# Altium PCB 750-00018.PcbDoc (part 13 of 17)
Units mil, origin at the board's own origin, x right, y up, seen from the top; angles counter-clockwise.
Board outline 7086.64 x 6299.21 mil, 8 copper layers (Top Layer, L2, L3, L4, L5, L6, L7, Bottom Layer), stack 60.6 mil thick; 1356 components, 1054 nets, 4851 pads, 4296 vias.
Unrouted connection lines stored in the file: 12.
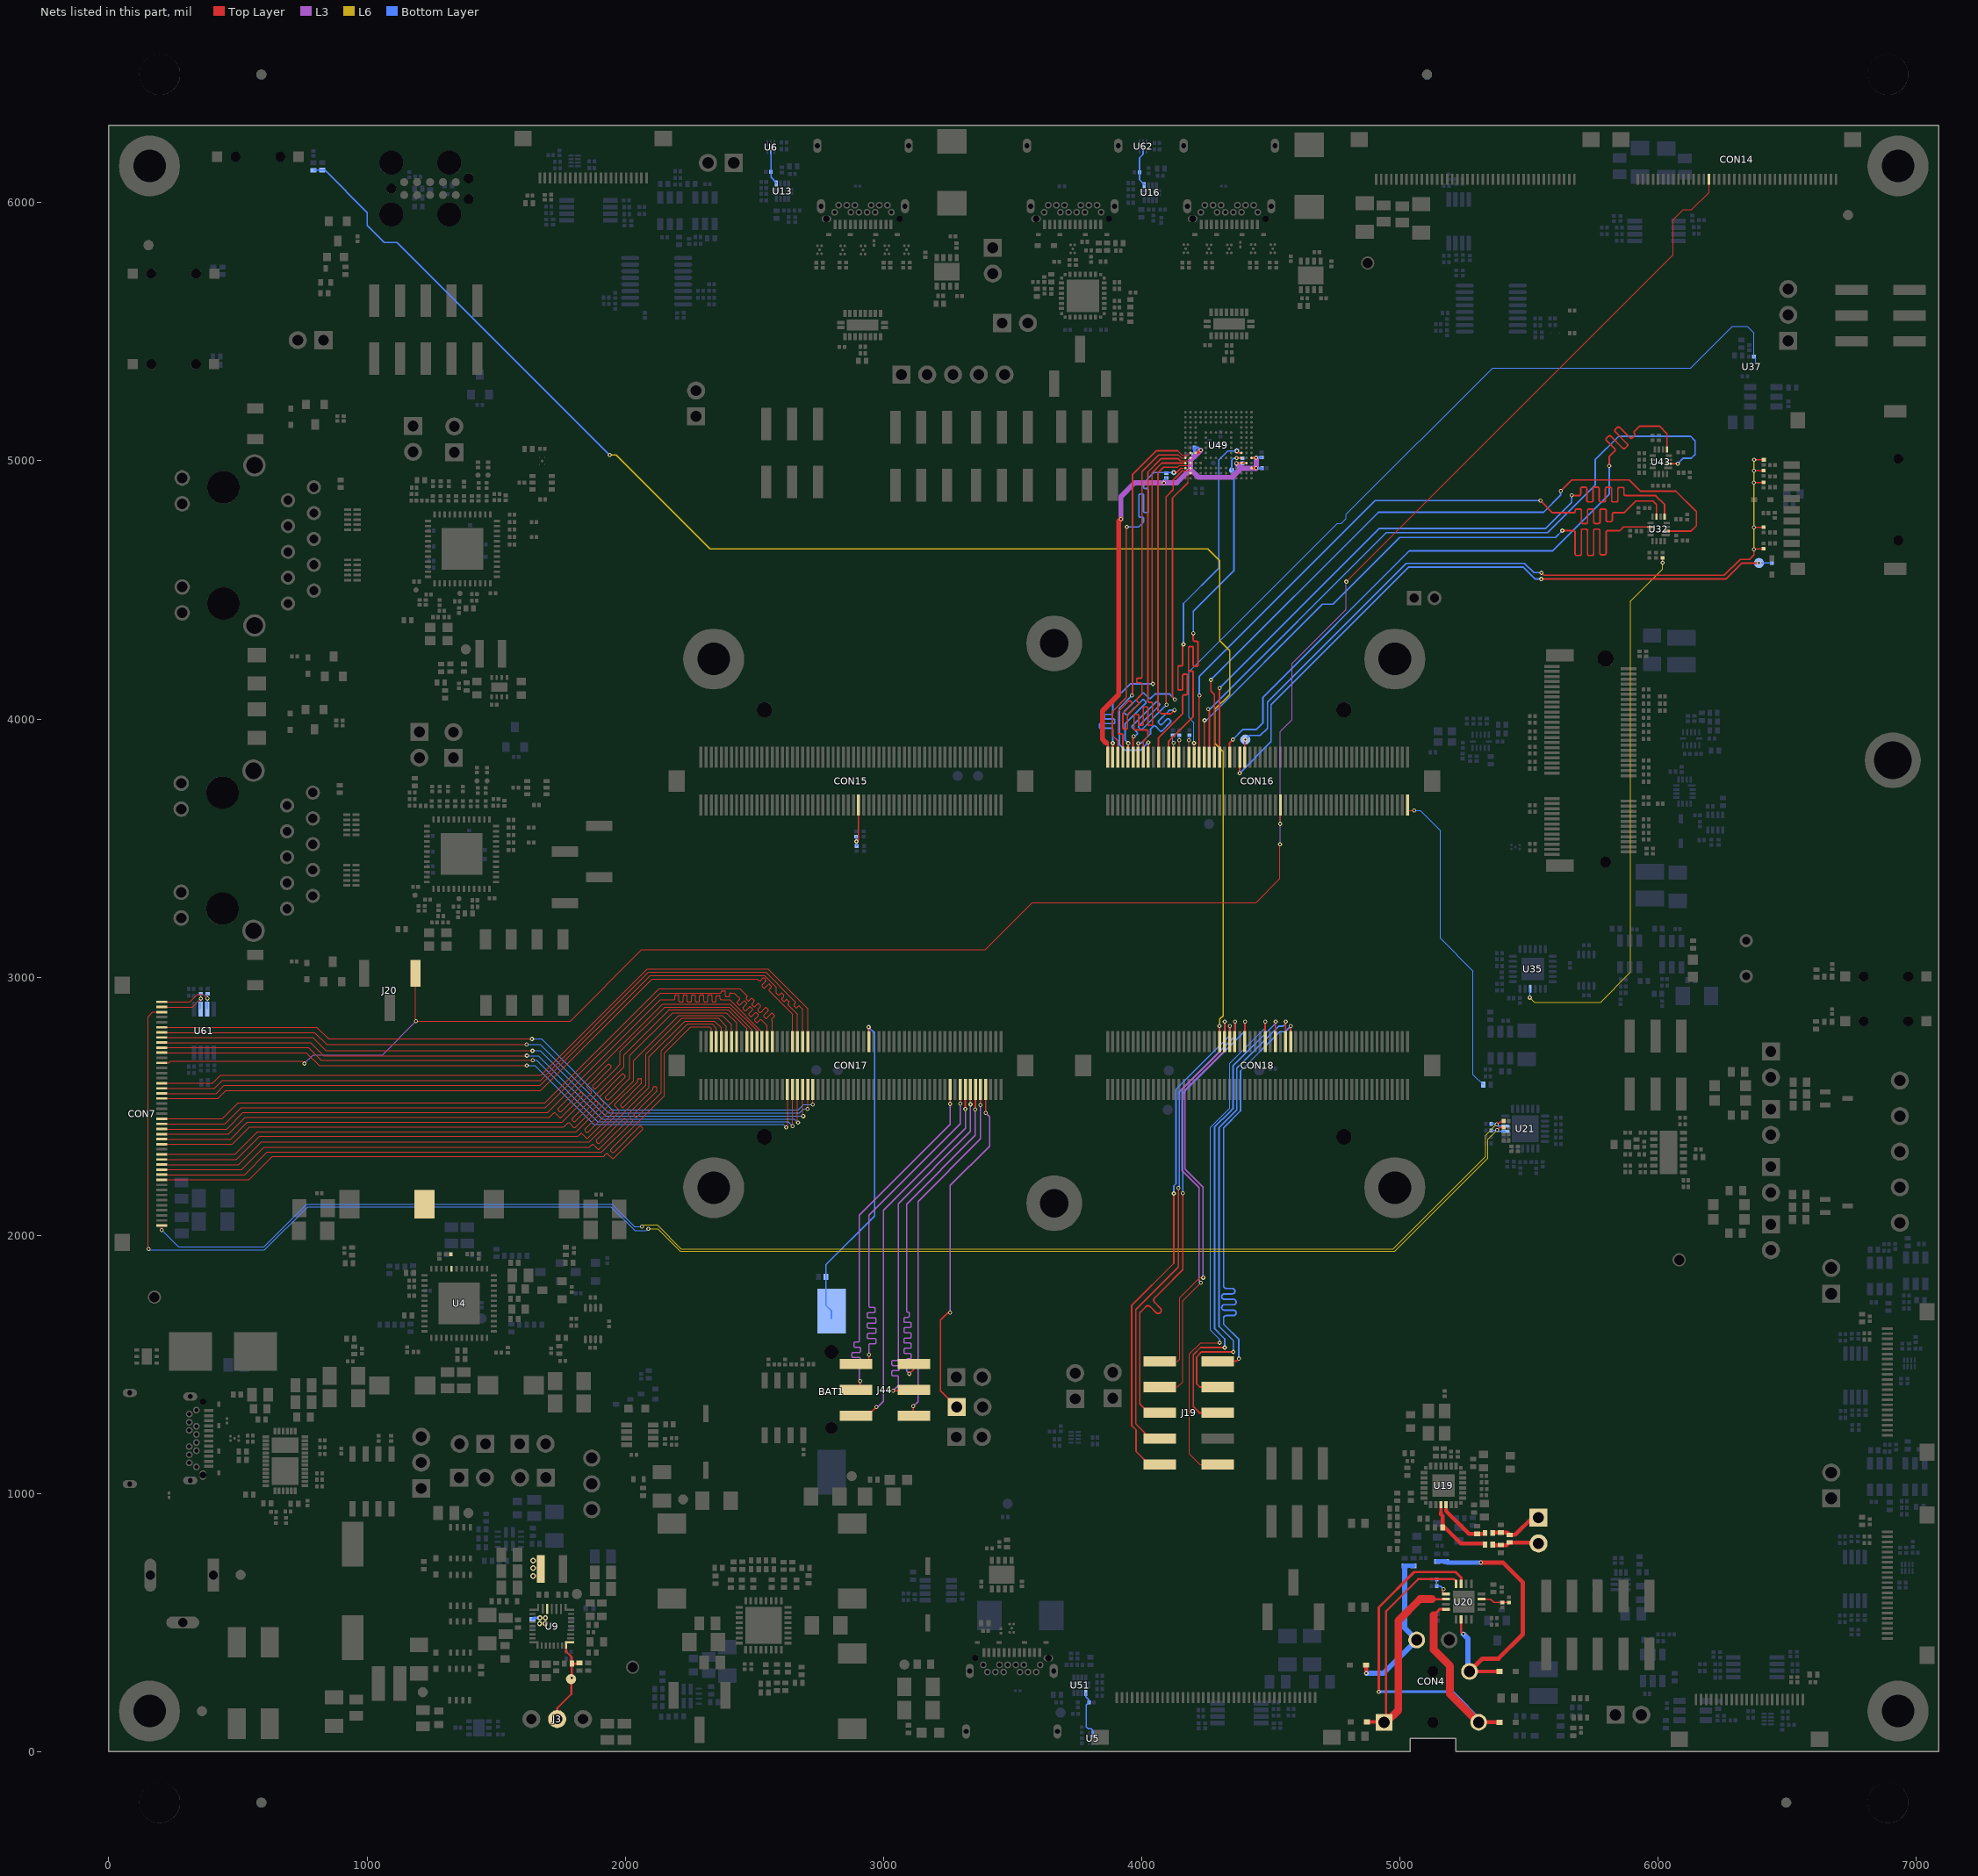
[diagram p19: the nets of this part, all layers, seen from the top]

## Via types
v1: diameter 16, hole 8, Top Layer to Bottom Layer, tented both sides, 3994 vias
v2: diameter 20, hole 10, Top Layer to Bottom Layer, tented both sides, 266 vias
v3: diameter 14, hole 7.87, Top Layer to Bottom Layer, tented both sides, 24 vias
v4: diameter 22, hole 12, Top Layer to Bottom Layer, tented both sides, 8 vias
v5: diameter 24, hole 12, Top Layer to Bottom Layer, tented both sides, 4 vias

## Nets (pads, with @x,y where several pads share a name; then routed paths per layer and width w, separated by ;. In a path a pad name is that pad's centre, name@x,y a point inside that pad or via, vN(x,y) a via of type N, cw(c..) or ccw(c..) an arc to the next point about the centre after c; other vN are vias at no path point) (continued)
RGB_B2: CON7.20 CON17.84 | length 2876
  Top Layer w4: CON7.20@204.84,2530.21 422.51,2530.21 453.35,2561.06 1671.84,2561.06 2104.1,2993.32 2511.42,2993.32 2516.58,2988.16 2517.99,2986.75 ccw(c2520.82,2989.58) 2523.65,2986.75 2532.61,2995.71 cw(c2535.44,2992.88) 2538.27,2995.71 2543.92,2990.05 cw(c2541.09,2987.22) 2543.92,2984.4 2529.86,2970.34 ccw(c2532.69,2967.51) 2529.86,2964.68 2535.52,2959.02 ccw(c2538.35,2961.85) 2541.18,2959.02 2553.44,2971.29 cw(c2556.27,2968.46) 2559.1,2971.29 2564.75,2965.63 cw(c2561.93,2962.8) 2564.75,2959.97 2557.59,2952.81 ccw(c2560.42,2949.98) 2557.59,2947.15 2568.48,2936.26 2647.64,2857.1 CON17.84@2647.64,2750.44
RGB_B3: CON7.19 CON17.82 | length 2876
  Top Layer w4: CON7.19@204.84,2549.9 415.29,2549.9 446.14,2580.74 1670.54,2580.74 2096.34,3006.54 2539.58,3006.54 2585.24,2960.88 2585.24,2938.18 2590.02,2933.4 2591.44,2931.98 ccw(c2594.27,2934.81) 2597.09,2931.98 2601.78,2936.67 cw(c2604.61,2933.84) 2607.43,2936.67 2613.09,2931.01 cw(c2610.26,2928.18) 2613.09,2925.35 2606.9,2919.16 ccw(c2609.73,2916.33) 2606.9,2913.5 2612.56,2907.85 ccw(c2615.38,2910.67) 2618.21,2907.85 2622.31,2911.94 cw(c2625.14,2909.11) 2627.97,2911.94 2633.62,2906.29 cw(c2630.8,2903.46) 2633.62,2900.63 2631.04,2898.04 ccw(c2633.86,2895.21) 2631.04,2892.38 2649.19,2874.23 2667.33,2856.09 CON17.82@2667.33,2750.44
RGB_B4: CON7.18 CON17.80 | length 2876
  Top Layer w4: CON7.18@204.84,2569.58 408.87,2569.58 439.72,2600.43 1671.91,2600.43 2090.99,3019.51 2543.34,3019.51 2645.82,2917.02 2658.55,2904.3 cw(c2655.72,2901.47) 2658.55,2898.64 2653.81,2893.89 ccw(c2656.63,2891.06) 2653.81,2888.24 2659.46,2882.58 ccw(c2662.29,2885.41) 2665.12,2882.58 2669.87,2887.33 cw(c2672.69,2884.5) 2675.52,2887.33 2684.26,2878.59 2687.01,2875.84 CON17.80@2687.01,2750.44
RGB_B5: CON7.17 CON17.78 | length 2876
  Top Layer w4: CON7.17@204.84,2589.26 401.66,2589.26 432.51,2620.11 1672.96,2620.11 2084.67,3031.82 2552.19,3031.82 2706.7,2877.32 CON17.78@2706.7,2750.44
"RGB_BL_PWM / LVDS_E_BL_PWM / PWM_2": CON7.13 CON14.26 CON16.70 J20.1 | length 8311.2
  Top Layer w4: CON7.13@204.84,2668.13 232.85,2668.13 239.73,2675.01 748.47,2675.01 v1(757.71,2665.78) ; v1@1187.99,2829.35 J20.1@1187.99,3015.01 ; v1(1189.57,2829.35) 1786.94,2829.35 2063.76,3106.18 3393.79,3106.18 3576.65,3289.03 4443.01,3289.03 4535.65,3381.68 v1(4535.65,3514.53) ; v1(4536.33,3593.67) 4536.8,3594.14 CON16.70@4536.8,3668.45 ; v1(4792.41,4531.9) 6058.03,5797.52 6058.03,5934.45 6096.47,5972.89 6129.93,5972.89 6196.76,6039.72 CON14.26@6196.76,6090.59
  L3 w4: v1(757.71,2665.78) 791.32,2699.39 1059.6,2699.39 v1(1189.57,2829.35) ; v1(4535.65,3514.53) 4536.33,3515.21 v1(4536.33,3593.67) 4536.33,3951.62 4582.66,3997.95 4582.66,4215.21 4792.41,4424.95 v1(4792.41,4531.9)
RGB_CS#: CON7.6 CON17.75 | length 2721.5
  Top Layer w4: CON7.6@204.84,2805.8 805.45,2805.8 850.45,2760.8 v1(1638.62,2760.8) ; v1(2726.17,2506.69) 2726.38,2506.9 CON17.75@2726.38,2565.4
  Bottom Layer w4: v1(1638.62,2760.8) 1674.63,2760.8 1949.87,2485.57 2669.27,2485.57 2690.4,2506.69 v1(2726.17,2506.69)
RGB_DE: CON7.8 CON17.79 | length 2714.9
  Top Layer w4: CON7.8@204.84,2766.43 789.15,2766.43 840.58,2714.99 v1(1640.8,2714.99) ; CON17.79@2687.01,2565.4 2687.01,2464.06 v1(2689.19,2461.88)
  Bottom Layer w4: v1(1640.8,2714.99) 1670.05,2714.99 1923.16,2461.88 v1(2689.19,2461.88)
RGB_DISP: CON7.9 CON17.81 | length 2722
  Top Layer w4: CON7.9@204.84,2746.75 780.99,2746.75 831.78,2695.96 v1(1618.79,2695.96) ; CON17.81@2667.33,2565.4 2667.33,2438.15 v1(2668.91,2436.57)
  Bottom Layer w4: v1(1618.79,2695.96) 1664.24,2695.96 1909.19,2451 2654.47,2451 v1(2668.91,2436.57)
RGB_G0: CON7.29 CON17.102 | length 2876
  Top Layer w4: CON7.29@204.84,2353.04 479.37,2353.04 545.75,2419.43 1761.46,2419.43 1775.26,2433.24 1776.68,2434.65 cw(c1780.07,2431.26) 1783.47,2434.65 1799.31,2418.81 ccw(c1802.7,2422.2) 1806.08,2418.8 1894.03,2506.74 ccw(c1890.63,2510.14) 1894.03,2513.53 1889.5,2518.06 ccw(c1886.11,2514.66) 1882.71,2518.06 1806.09,2441.44 cw(c1802.7,2444.83) 1799.31,2441.44 1794.78,2445.96 cw(c1798.17,2449.36) 1794.78,2452.75 1895.35,2553.32 1896.76,2554.73 1994.34,2652.31 1994.34,2698.26 2169.49,2873.42 2397.71,2873.42 2470.47,2800.65 CON17.102@2470.47,2750.44
RGB_G1: CON7.28 CON17.100 | length 2876.4
  Top Layer w4: CON7.28@204.84,2372.73 471.22,2372.73 536.6,2438.11 1755.14,2438.11 1866.45,2549.43 1867.86,2550.84 ccw(c1864.47,2554.23) 1867.87,2557.62 1852.02,2573.47 cw(c1855.42,2576.86) 1852.02,2580.25 1932.91,2661.14 cw(c1936.3,2657.75) 1939.7,2661.14 1944.22,2656.62 cw(c1940.83,2653.22) 1944.22,2649.83 1874.65,2580.26 ccw(c1878.05,2576.86) 1874.65,2573.47 1879.18,2568.94 ccw(c1882.57,2572.34) 1885.97,2568.94 1968.95,2651.93 1970.37,2653.34 1979.86,2662.84 1979.86,2712.01 2152.29,2884.44 2402.59,2884.44 2489.16,2797.87 2489.16,2751.44 CON17.100@2490.16,2750.44
RGB_G2: CON7.27 CON17.98 | length 2876
  Top Layer w4: CON7.27@204.84,2392.41 463.06,2392.41 527.48,2456.83 1705.85,2456.83 1720.83,2471.81 1722.25,2473.23 cw(c1725.64,2469.83) 1729.03,2473.23 1744.86,2457.4 ccw(c1748.27,2460.78) 1751.65,2457.38 1835.71,2541.44 ccw(c1832.32,2544.83) 1835.71,2548.23 1831.19,2552.75 ccw(c1827.79,2549.36) 1824.4,2552.75 1751.66,2480.02 cw(c1748.27,2483.41) 1744.87,2480.02 1740.35,2484.54 cw(c1743.74,2487.94) 1740.35,2491.33 1837.05,2588.03 1838.46,2589.44 2145.39,2896.38 2406.99,2896.38 2509.85,2793.52 CON17.98@2509.85,2750.44
RGB_G3: CON7.26 CON17.96 | length 2877.5
  Top Layer w4: CON7.26@204.84,2412.1 456,2412.1 519.45,2475.55 1698.59,2475.55 2135.65,2912.61 2185.99,2912.61 2187.99,2912.61 ccw(c2187.99,2916.61) 2191.99,2916.61 2191.99,2926.97 cw(c2195.99,2926.97) 2195.99,2930.97 2203.99,2930.97 cw(c2203.99,2926.97) 2207.99,2926.97 2207.99,2908.38 ccw(c2211.99,2908.38) 2211.99,2904.38 2219.99,2904.38 ccw(c2219.99,2908.38) 2223.99,2908.38 2223.99,2926.97 cw(c2227.99,2926.97) 2227.99,2930.97 2235.99,2930.97 cw(c2235.99,2926.97) 2239.99,2926.97 2239.99,2908.38 ccw(c2243.99,2908.38) 2243.99,2904.38 2251.99,2904.38 ccw(c2251.99,2908.38) 2255.99,2908.38 2255.99,2926.97 cw(c2259.99,2926.97) 2259.99,2930.97 2267.99,2930.97 cw(c2267.99,2926.97) 2271.99,2926.97 2271.99,2908.38 ccw(c2275.99,2908.38) 2275.99,2904.38 2283.99,2904.38 ccw(c2283.99,2908.38) 2287.99,2908.38 2287.99,2926.97 cw(c2291.99,2926.97) 2291.99,2930.97 2299.99,2930.97 cw(c2299.99,2926.97) 2303.99,2926.97 2303.99,2908.38 ccw(c2307.99,2908.38) 2307.99,2904.38 2315.99,2904.38 ccw(c2315.99,2908.38) 2319.99,2908.38 2319.99,2926.97 cw(c2323.99,2926.97) 2323.99,2930.97 2331.99,2930.97 cw(c2331.99,2926.97) 2335.99,2926.97 2335.99,2908.38 ccw(c2339.99,2908.38) 2339.99,2904.38 2347.99,2904.38 ccw(c2347.99,2908.38) 2351.99,2908.38 2351.99,2924.51 cw(c2355.99,2924.51) 2355.99,2928.51 2363.99,2928.51 cw(c2363.99,2924.51) 2367.99,2924.51 2367.99,2916.61 ccw(c2371.99,2916.61) 2371.99,2912.61 2381.78,2912.61 2404.57,2912.61 2529.53,2787.65 CON17.96@2529.53,2750.44
RGB_G4: CON7.25 CON17.94 | length 2876
  Top Layer w4: CON7.25@204.84,2431.78 449.32,2431.78 511.81,2494.27 1691.07,2494.27 2135.77,2938.97 2366.1,2938.97 2368.1,2938.97 ccw(c2368.1,2942.97) 2372.1,2942.97 2372.1,2943.24 cw(c2376.1,2943.24) 2376.1,2947.24 2384.1,2947.24 cw(c2384.1,2943.24) 2388.1,2943.24 2388.1,2928.48 ccw(c2392.1,2928.48) 2392.1,2924.48 2400.1,2924.48 ccw(c2400.1,2928.48) 2404.1,2928.48 2404.1,2934.97 cw(c2408.1,2934.97) 2408.1,2938.97 2422.06,2938.97 2422.25,2938.97 2429.32,2931.9 2442.05,2919.17 cw(c2439.22,2916.34) 2442.05,2913.51 2433.53,2904.99 ccw(c2436.36,2902.16) 2433.53,2899.34 2439.19,2893.68 ccw(c2442.02,2896.51) 2444.85,2893.68 2457.99,2906.83 cw(c2460.82,2904) 2463.65,2906.83 2469.31,2901.17 cw(c2466.48,2898.34) 2469.31,2895.51 2456.16,2882.37 ccw(c2458.99,2879.54) 2456.16,2876.71 2461.82,2871.05 ccw(c2464.64,2873.88) 2467.47,2871.05 2480.62,2884.2 cw(c2483.45,2881.37) 2486.28,2884.2 2491.93,2878.54 cw(c2489.1,2875.71) 2491.93,2872.88 2478.79,2859.74 ccw(c2481.62,2856.91) 2478.79,2854.08 2484.44,2848.42 ccw(c2487.27,2851.25) 2490.1,2848.42 2503.25,2861.57 cw(c2506.08,2858.74) 2508.9,2861.57 2514.56,2855.91 cw(c2511.73,2853.09) 2514.56,2850.26 2501.41,2837.11 ccw(c2504.24,2834.28) 2501.41,2831.45 2507.07,2825.8 ccw(c2509.9,2828.63) 2512.73,2825.8 2521.25,2834.31 cw(c2524.07,2831.49) 2526.9,2834.31 2541.79,2819.43 2549.22,2812 CON17.94@2549.22,2750.44
RGB_G5: CON7.24 CON17.92 | length 2876
  Top Layer w4: CON7.24@204.84,2451.47 439.13,2451.47 500.56,2512.89 1689.3,2512.89 2131.76,2955.35 2444.01,2955.35 2458.09,2941.27 2470.82,2928.54 cw(c2467.99,2925.71) 2470.82,2922.88 2468.86,2920.92 ccw(c2471.69,2918.09) 2468.86,2915.27 2474.52,2909.61 ccw(c2477.35,2912.44) 2480.18,2909.61 2486.72,2916.16 cw(c2489.55,2913.33) 2492.38,2916.16 2498.04,2910.5 cw(c2495.21,2907.67) 2498.04,2904.84 2491.49,2898.3 ccw(c2494.32,2895.47) 2491.49,2892.64 2497.15,2886.98 ccw(c2499.98,2889.81) 2502.81,2886.98 2512.05,2896.23 ; 2512.05,2896.23 cw(c2514.88,2893.4) 2517.71,2896.23 2523.36,2890.57 cw(c2520.53,2887.74) 2523.36,2884.91 2514.12,2875.67 ccw(c2516.95,2872.84) 2514.12,2870.01 2519.78,2864.35 ccw(c2522.61,2867.18) 2525.43,2864.35 2541.59,2880.51 cw(c2544.42,2877.68) 2547.25,2880.51 2552.91,2874.86 cw(c2550.08,2872.03) 2552.91,2869.2 2536.75,2853.04 ccw(c2539.58,2850.21) 2536.75,2847.38 2542.4,2841.73 ccw(c2545.23,2844.56) 2548.06,2841.73 2565.04,2858.7 cw(c2567.87,2855.87) 2570.69,2858.7 2576.35,2853.05 cw(c2573.52,2850.22) 2576.35,2847.39 2566.99,2838.03 ccw(c2569.82,2835.2) 2566.99,2832.37 2568.9,2830.46 2568.9,2815.07 CON17.92@2568.9,2750.44
RGB_HDMI_HPD: CON7.45 R546.1 R554.2 U21.22 | length 5699.6
  Top Layer w4: v1(204.67,2020.58) 204.84,2020.75 CON7.45@204.84,2038.21
  Top Layer w5: v1(5374.88,2429.76) 5378.82,2429.76 5391.93,2442.87 R554.2@5401.82,2442.87
  L6 w4: v1(2064.93,2033.87) 2071.72,2040.65 2123.68,2040.65 2216.49,1947.84 4973.82,1947.84 5331.71,2305.73 5331.71,2387.96 5373.51,2429.76 v1(5374.88,2429.76)
  Bottom Layer w4: v1(204.67,2020.58) 268.72,1956.53 601.58,1956.53 766.25,2121.2 1949.23,2121.2 2036.56,2033.87 v1(2064.93,2033.87)
  Bottom Layer w5: R546.1@5352.93,2432.14 5372.5,2432.14 v1(5374.88,2429.76) 5381.62,2423.01 U21.22@5408.49,2423.01
RGB_HSYNC: CON7.10 CON17.83 | length 2712.4
  Top Layer w4: CON7.10@204.84,2727.06 772.84,2727.06 821.99,2677.91 v1(1641,2677.91) ; CON17.83@2647.64,2565.4 2646.26,2564.02 2647.97,2562.31 v1(2647.97,2423.23)
  Bottom Layer w4: v1(1641,2677.91) 1656.36,2677.91 1893.62,2440.65 2630.56,2440.65 v1(2647.97,2423.23)
RGB_INT: CON7.3 R545.1 R553.2 U21.21 | length 6656.2
  Top Layer w4: v1(154.15,1946.95) 151.69,1949.41 151.69,2847.33 169.22,2864.86 CON7.3@204.84,2864.86
  Top Layer w5: v1(5376.23,2407.74) 5386.3,2417.81 R553.2@5401.82,2417.81
  L6 w4: v1(2089.15,2025.25) 2126.14,2025.25 2212.7,1938.68 4981,1938.68 5341.32,2299.01 5341.32,2372.84 v1(5376.23,2407.74)
  Bottom Layer w4: v1(154.15,1946.95) 156.7,1944.4 603.42,1944.4 770.28,2111.26 1944.34,2111.26 2037.1,2018.5 2082.41,2018.5 v1(2089.15,2025.25)
  Bottom Layer w5: R545.1@5352.93,2406.77 5375.25,2406.77 v1(5376.23,2407.74) 5380.63,2403.33 U21.21@5408.49,2403.33
RGB_R0: CON7.36 CON17.116 | length 2876
  Top Layer w4: CON7.36@204.84,2215.25 542.88,2215.25 633.69,2306.06 1916.69,2306.06 1924.44,2313.81 1925.85,2315.23 cw(c1929.25,2311.83) 1932.64,2315.23 1948.48,2299.38 ccw(c1951.87,2302.78) 1955.26,2299.38 2066.37,2410.49 ccw(c2062.98,2413.89) 2066.37,2417.28 2061.85,2421.81 ccw(c2058.45,2418.41) 2055.06,2421.81 1955.27,2322.02 cw(c1951.87,2325.41) 1948.48,2322.02 1943.95,2326.54 cw(c1947.35,2329.94) 1943.95,2333.33 2052.06,2441.44 2053.48,2442.85 2151.01,2540.39 2151.01,2705.61 2252.8,2807.4 2325.94,2807.4 2332.68,2800.66 CON17.116@2332.68,2750.44
RGB_R1: CON7.35 CON17.114 | length 2876.3
  Top Layer w4: CON7.35@204.84,2234.93 525.89,2234.93 613.61,2322.66 1909.09,2322.66 2025.78,2439.34 2027.19,2440.76 ccw(c2023.8,2444.15) 2027.19,2447.54 2011.36,2463.37 cw(c2014.75,2466.78) 2011.34,2470.16 2105.65,2564.47 ccw(c2102.25,2567.85) 2107.05,2567.85 2107.05,2570.77 cw(c2111.85,2570.77) 2111.85,2575.57 2118.25,2575.57 cw(c2118.25,2570.77) 2123.05,2570.77 2123.05,2561.23 cw(c2118.25,2561.23) 2121.65,2557.84 2033.98,2470.17 ccw(c2037.38,2466.78) 2033.98,2463.38 2038.51,2458.86 ccw(c2041.9,2462.25) 2045.3,2458.86 2137.65,2551.21 ccw(c2134.25,2554.6) 2139.05,2554.6 2139.05,2601.81 2139.05,2603.81 2139.05,2716.51 2241.15,2818.61 2336.77,2818.61 2352.36,2803.02 CON17.114@2352.36,2750.44
RGB_R2: CON7.34 CON17.112 | length 2876
  Top Layer w4: CON7.34@204.84,2254.62 513.67,2254.62 600.4,2341.35 1861.16,2341.35 1869.2,2349.39 1870.62,2350.8 cw(c1874.01,2347.41) 1877.41,2350.8 1893.25,2334.96 ccw(c1896.64,2338.36) 1900.02,2334.95 2005.28,2440.21 ccw(c2001.88,2443.6) 2005.28,2447 2000.75,2451.52 ccw(c1997.36,2448.13) 1993.96,2451.52 1900.03,2357.59 cw(c1896.64,2360.99) 1893.25,2357.59 1888.72,2362.12 cw(c1892.11,2365.51) 1888.72,2368.9 1992.59,2472.77 1994,2474.19 2092.55,2572.74 2092.55,2691.23 2231.54,2830.22 2345.86,2830.22 2372.05,2804.03 CON17.112@2372.05,2750.44
RGB_R3: CON7.33 CON17.110 | length 2876.3
  Top Layer w4: CON7.33@204.84,2274.3 501.92,2274.3 590.52,2362.91 1860.2,2362.91 1974.1,2476.8 1975.51,2478.21 ccw(c1972.12,2481.61) 1975.52,2484.99 1959.68,2500.83 cw(c1963.07,2504.24) 1959.66,2507.62 2046.19,2594.15 ccw(c2042.78,2597.53) 2047.58,2597.53 2047.58,2601.75 cw(c2052.38,2601.75) 2052.38,2606.55 2058.78,2606.55 cw(c2058.78,2601.75) 2063.58,2601.75 2063.58,2590.9 cw(c2058.78,2590.9) 2062.19,2587.52 1982.3,2507.63 ccw(c1985.69,2504.24) 1982.3,2500.84 1986.82,2496.32 ccw(c1990.22,2499.71) 1993.61,2496.32 2078.19,2580.89 ccw(c2074.78,2584.28) 2079.58,2584.28 2079.58,2631.55 2079.58,2701.42 2219.25,2841.09 2360.38,2841.09 2391.73,2809.74 CON17.110@2391.73,2750.44
RGB_R4: CON7.32 CON17.108 | length 2876
  Top Layer w4: CON7.32@204.84,2293.99 494.46,2293.99 584.19,2383.73 1816.75,2383.73 1824.86,2391.84 1826.27,2393.25 cw(c1829.67,2389.86) 1833.05,2393.26 1848.91,2377.41 ccw(c1852.3,2380.81) 1855.68,2377.41 1952.29,2474.01 ccw(c1948.89,2477.4) 1952.29,2480.8 1947.76,2485.32 ccw(c1944.37,2481.93) 1940.97,2485.32 1855.69,2400.04 cw(c1852.3,2403.44) 1848.9,2400.04 1844.38,2404.57 cw(c1847.77,2407.96) 1844.38,2411.36 1961.15,2528.13 1962.56,2529.54 2031.6,2598.58 2031.6,2676.31 2207.43,2852.14 2375.46,2852.14 2411.42,2816.19 CON17.108@2411.42,2750.44
RGB_R5: CON7.31 CON17.106 | length 2876
  Top Layer w4: CON7.31@204.84,2313.67 488.02,2313.67 575.66,2401.31 1809.84,2401.31 1915.17,2506.65 1916.59,2508.06 ccw(c1913.19,2511.45) 1916.59,2514.85 1900.76,2530.68 cw(c1904.14,2534.08) 1900.74,2537.47 1986.88,2623.61 cw(c1990.27,2620.21) 1993.67,2623.61 1998.19,2619.08 cw(c1994.8,2615.69) 1998.19,2612.29 1923.38,2537.48 ccw(c1926.77,2534.08) 1923.38,2530.69 1927.9,2526.16 ccw(c1931.3,2529.56) 1934.69,2526.16 2016.55,2608.02 2017.96,2609.43 2017.96,2696.31 2184.11,2862.46 2391.93,2862.46 2431.1,2823.29 CON17.106@2431.1,2750.44
RGB_RESET#: CON7.7 CON17.77 | length 2712.1
  Top Layer w4: CON7.7@204.84,2786.12 797.3,2786.12 843.64,2739.78 v1(1617.8,2739.78) ; v1(2705.53,2489.98) 2706.7,2491.15 CON17.77@2706.7,2565.4
  Bottom Layer w4: v1(1617.8,2739.78) 1669.93,2739.78 1935.24,2474.47 2674.65,2474.47 2690.16,2489.98 v1(2705.53,2489.98)
RGB_SCL: CON7.2 R506.2 U61.2 | length 225.1
  Top Layer w4: CON7.2@204.84,2884.54 323.73,2884.54 v1(356.46,2917.28)
  Bottom Layer w4: U61.2@355.31,2876.44 355.31,2916.13 v1(356.46,2917.28) 356.46,2935.59 R506.2@356.68,2935.8
RGB_SDA: CON7.1 R505.2 U61.3 | length 255.9
  Top Layer w4: CON7.1@204.84,2904.23 313.85,2904.23 342.96,2933.34 366.95,2933.34 381.49,2918.8 v1(381.49,2917.46)
  Bottom Layer w4: U61.3@380.91,2876.44 380.91,2916.87 v1(381.49,2917.46) 382.43,2918.39 R505.2@382.43,2935.65
RGB_VSYNC: CON7.11 CON17.85 | length 2688.2
  Top Layer w4: CON7.11@204.84,2707.38 764.69,2707.38 814.58,2657.48 v1(1618.39,2657.48) ; v1(2623.41,2418.05) 2628.64,2423.28 2628.64,2564.72 CON17.85@2627.96,2565.4
  Bottom Layer w4: v1(1618.39,2657.48) 1650.58,2657.48 1878.49,2429.57 2611.89,2429.57 v1(2623.41,2418.05)
RING1: C204.2 CON4.3 D19.1 FB6.2 | length 624.9
  Top Layer w15: D19.1@4869.52,335.75 4869.52,305.06 v1(4870.38,304.2) ; CON4.3@5060.92,442.88 CON4.3@5065.14,438.65
  Bottom Layer w17: C204.2@5018.08,720.01 FB6.2@5051.76,720.01
  Bottom Layer w20: v1@4869.73,304.2 v1(4870.38,304.2) 4936,304.2 CON4.3@5064.87,433.07 5019.14,478.8 C204.2@5019.14,718.95
RING2: CON4.4 D18.1 U20.7 U20.12 | length 1816.8
  Top Layer w10: v1(4918.46,231.94) 4918.46,559.13 5055.46,696.12 5215.97,696.12 5237.16,674.93 U20.7@5237.16,650.24 ; 5131.08,529.42 5153.47,551.81 U20.12@5179.39,551.81 ; CON4.4@5303.75,114.17 CON4.4@5305.03,114.17 CON4.4@5306.31,114.17
  Top Layer w15: CON4.4@5306.31,114.17 D18.1@5386.44,114.17
  Top Layer w30: 5131.08,529.42 5131.08,395.53 5194.06,332.55 5194.06,223.86 CON4.4@5303.75,114.17
  Bottom Layer w10: v1(4918.46,231.94) 4919.85,233.32 5203,233.32 CON4.4@5322.15,114.17
RTC_PWR: BAT1.1 C221.2 CON17.54 | length 1282.5
  Top Layer w6: v1(2942.54,2806.77) 2942.92,2806.39 CON17.54@2942.92,2750.44
  Bottom Layer w6: BAT1.1@2798.66,1677.01 BAT1.1@2798.66,1707.46 2777.33,1728.79 C221.2@2777.33,1840.06 2777.33,1886.92 2965.51,2075.09 2965.51,2783.8 v1(2942.54,2806.77)
SCL3: R192.2 R196.2 U20.9 | length 87.5
  Top Layer w5: v1(5168.97,629.81) 5164.6,625.44 5164.6,617.73 5171.46,610.87 U20.9@5178.11,610.87
  Bottom Layer w5: R196.2@5142.06,667.17 5142.28,666.95 R192.2@5142.28,641.5 5157.28,641.5 v1(5168.97,629.81)
SDA3: R194.2 R197.2 U20.3 | length 111.8
  Top Layer w5: U20.3@5315.9,591.18 5351.41,591.18 5364.1,578.49 R197.2@5397.35,578.49 R194.2@5422.49,578.49
SDIO_A_CD#: CON16.53 R304.1 TP22.1 | length 2583.1
  Top Layer w6.5: v1(4379.47,3790.22) 4379.92,3790.68 CON16.53@4379.92,3851.92 ; v1(5547.31,4542.13) 5547.74,4542.56 6263.1,4542.56 6324.61,4604.06 v1(6390.72,4604.06)
  Bottom Layer w5: v1(6390.72,4604.06) 6440.65,4604.06 R304.1@6440.88,4604.29
  Bottom Layer w6.5: v1(4379.47,3790.22) 4500.98,3911.74 4500.98,4056.17 5032.85,4588.03 5478.29,4588.03 5524.2,4542.13 v1(5547.31,4542.13)
SDIO_A_CLK: CON16.49 U43.5 | length 2744.6
  Top Layer w6: CON16.49@4340.55,3851.92 4340.55,3908.02 v1(4352.7,3920.17) ; v1(5810.46,4980.15) 5810.46,5016.41 5829.82,5035.77 5831.94,5037.89 ccw(c5827.7,5042.14) 5831.94,5046.38 5799.89,5078.43 cw(c5804.14,5082.67) 5799.89,5086.91 5808.38,5095.4 cw(c5812.62,5091.15) 5816.86,5095.4 5863.49,5048.77 ; 5863.49,5048.77 ccw(c5867.73,5053.02) 5871.97,5048.77 ; 5871.97,5048.77 5880.46,5057.26 ccw(c5876.21,5061.5) 5880.46,5065.74 5833.84,5112.37 cw(c5838.08,5116.61) 5833.83,5120.85 5842.32,5129.34 cw(c5846.56,5125.09) 5850.81,5129.34 5891.6,5088.54 ccw(c5895.84,5092.79) 5900.09,5088.54 5908.57,5097.03 ccw(c5904.33,5101.27) 5908.57,5105.51 5908.31,5105.78 cw(c5912.55,5110.02) 5908.31,5114.26 5918.56,5124.51 5928.32,5134.27 6005.21,5134.27 6034.55,5104.94 U43.5@6034.55,5043.55
  Bottom Layer w6: v1(4352.7,3920.17) 4392.2,3959.67 4444.27,3959.67 4469.62,3985.01 4469.62,4083.95 5037.32,4651.65 5591.8,4651.65 5810.46,4870.31 v1(5810.46,4980.15)
SDIO_A_CMD: CON16.41 U43.2 | length 2744.6
  Top Layer w6: v1(4257.39,4038.65) 4261.81,4034.23 CON16.41@4261.81,3851.92 ; U43.2@6042.42,4988.44 v1(6075.85,4988.44)
  Bottom Layer w6: v1(4257.39,4038.65) 4264.24,4038.65 4947.21,4721.63 5571.8,4721.63 5755.91,4905.74 5755.91,5003.51 5847.37,5094.97 6125.52,5094.97 6143.01,5077.48 6143.01,5024.73 6128.48,5010.2 6097.62,5010.2 v1(6075.85,4988.44)
SDIO_A_D0: CON16.43 U32.2 | length 2744.4
  Top Layer w6: v1(4268.18,4151.45) 4268.18,4108.31 4281.5,4095 CON16.43@4281.5,3851.92 ; v1(5622.5,4883.34) 5664.91,4925.75 5888.43,4925.75 5932.01,4882.17 6069.18,4882.17 6147.85,4803.51 6147.85,4747.95 6127.87,4727.96 U32.2@6033.19,4727.96
  Bottom Layer w6: v1(4268.18,4151.45) 4268.18,4152.32 4916.73,4800.87 5556,4800.87 5622.5,4867.36 v1(5622.5,4883.34)
SDIO_A_D1: CON16.45 U32.5 | length 2744.6
  Top Layer w6: CON16.45@4301.18,3851.92 4301.18,4119.6 v1(4301.59,4120) ; v1(5665.13,4866.7) 5666.8,4865.03 5690.84,4865.03 5693.84,4865.03 ccw(c5693.84,4871.03) 5699.84,4871.03 5699.84,4891.79 cw(c5705.84,4891.79) 5705.84,4897.79 5717.84,4897.79 cw(c5717.84,4891.79) 5723.84,4891.79 5723.84,4846.64 ccw(c5729.84,4846.64) 5729.84,4840.64 5741.84,4840.64 ccw(c5741.84,4846.64) 5747.84,4846.64 5747.84,4891.79 cw(c5753.84,4891.79) 5753.84,4897.79 5765.84,4897.79 cw(c5765.84,4891.79) 5771.84,4891.79 5771.84,4846.64 ccw(c5777.84,4846.64) 5777.84,4840.64 5789.84,4840.64 ccw(c5789.84,4846.64) 5795.84,4846.64 5795.84,4891.79 cw(c5801.84,4891.79) 5801.84,4897.79 5813.84,4897.79 cw(c5813.84,4891.79) 5819.84,4891.79 5819.84,4846.64 ccw(c5825.84,4846.64) 5825.84,4840.64 5837.84,4840.64 ccw(c5837.84,4846.64) 5843.84,4846.64 5843.84,4890.71 cw(c5849.84,4890.71) 5849.84,4896.71 5861.84,4896.71 cw(c5861.84,4890.71) 5867.84,4890.71 5867.84,4871.03 ccw(c5873.84,4871.03) 5873.84,4865.03 5887.19,4865.03 5990.65,4865.03 6025.31,4830.37 U32.5@6025.31,4783.08
  Bottom Layer w6: v1(4301.59,4120) 4919.07,4737.48 5563.09,4737.48 5665.13,4839.52 v1(5665.13,4866.7)
SDIO_A_D2: CON16.37 U32.7 | length 2744.6
  Top Layer w6: CON16.37@4222.44,3851.92 4222.44,4089.97 v1(4223.41,4090.94) ; v1(5544.14,4845.9) 5591.22,4798.82 5669.72,4798.82 5672.72,4798.82 ccw(c5672.72,4804.82) 5678.72,4804.82 5678.72,4807.16 cw(c5684.72,4807.16) 5684.72,4813.16 5696.72,4813.16 cw(c5696.72,4807.16) 5702.72,4807.16 5702.72,4763 ccw(c5708.72,4763) 5708.72,4757 5720.72,4757 ccw(c5720.72,4763) 5726.72,4763 5726.72,4807.16 cw(c5732.72,4807.16) 5732.72,4813.16 5744.72,4813.16 cw(c5744.72,4807.16) 5750.72,4807.16 5750.72,4763 ccw(c5756.72,4763) 5756.72,4757 5768.72,4757 ccw(c5768.72,4763) 5774.72,4763 5774.72,4807.16 cw(c5780.72,4807.16) 5780.72,4813.16 5792.72,4813.16 cw(c5792.72,4807.16) 5798.72,4807.16 5798.72,4770.36 ccw(c5804.72,4770.36) 5804.72,4764.36 5816.72,4764.36 ccw(c5816.72,4770.36) 5822.72,4770.36 5822.72,4792.82 cw(c5828.72,4792.82) 5828.72,4798.82 5843.4,4798.82 5867.52,4798.82 5913.17,4844.46 5979.72,4844.46 5993.82,4830.37 U32.7@5993.82,4783.08
  Bottom Layer w6: v1(4223.41,4090.94) 4222.51,4091.85 4222.51,4164.42 4903.99,4845.9 v1(5544.14,4845.9)
SDIO_A_D3: CON16.39 U32.10 | length 2744.6
  Top Layer w6: CON16.39@4242.13,3851.92 4242.13,3993.99 v1(4243.17,3995.03) ; v1(5628.68,4729.42) 5645.43,4729.42 5672.43,4729.42 cw(c5672.43,4723.42) 5678.43,4723.42 5678.43,4639.58 ccw(c5684.43,4639.58) 5684.43,4633.58 5696.43,4633.58 ccw(c5696.43,4639.58) 5702.43,4639.58 5702.43,4729.6 cw(c5708.43,4729.6) 5708.43,4735.6 5720.43,4735.6 cw(c5720.43,4729.6) 5726.43,4729.6 5726.43,4639.58 ccw(c5732.43,4639.58) 5732.43,4633.58 5744.43,4633.58 ccw(c5744.43,4639.58) 5750.43,4639.58 5750.43,4729.6 cw(c5756.43,4729.6) 5756.43,4735.6 5768.43,4735.6 cw(c5768.43,4729.6) 5774.43,4729.6 5774.43,4642.04 ccw(c5780.43,4642.04) 5780.43,4636.04 5792.43,4636.04 ccw(c5792.43,4642.04) 5798.43,4642.04 5798.43,4723.42 cw(c5804.43,4723.42) 5804.43,4729.42 5848.94,4729.42 5852.33,4729.42 5866.62,4743.71 U32.10@5970.19,4743.71
  Bottom Layer w6: v1(4243.17,3995.03) 4250.52,3995.03 4700.14,4444.65 4739.93,4444.65 4998.43,4703.15 5602.41,4703.15 v1(5628.68,4729.42)
SDIO_A_IOPWR: CON16.55 R424.2 R442.2 R450.2 R527.2 R529.2 TP25.1 | length 2988.3
  Top Layer w5: CON16.55@4399.61,3851.92 4399.61,3918.49 v1(4401.31,3920.19) ; v1(5548.41,4566.25) 5558.41,4556.25 6255.71,4556.25 6318.27,4618.82 6354.27,4618.82 6371.22,4635.77 v1(6371.22,4657.63) ; v1(6370.89,4961.46) 6371.12,4961.7 R529.2@6408.81,4961.7 ; v1(6371.33,4915.28) 6372.04,4915.99 R424.2@6408.29,4915.99 ; v1(6371.63,5004.1) 6371.72,5004.01 R527.2@6408.93,5004.01 ; v1@6371.93,4658.34 R450.2@6408.18,4658.34 ; v1@6372.01,4742.54 R442.2@6408.26,4742.54
  L6 w5: v1(6371.22,4657.63) 6371.22,4741.76 v1(6371.3,4741.84) v1@6371.3,4915.26 ; v1(6371.33,4915.28) 6371.33,4961.02 v1(6370.89,4961.46) 6370.89,5003.37 v1(6371.63,5004.1)
  Bottom Layer w5: v1(4401.31,3920.19) 4416.91,3935.79 4459.17,3935.79 4486.86,3963.48 4486.86,4066.12 5023.97,4603.22 5481.57,4603.22 5518.55,4566.25 v1(5548.41,4566.25)
SDIO_A_PWR_EN: CON16.35 R538.1 U37.1 | length 3226.5
  Top Layer w4: v1(4202.45,3906.37) 4202.76,3906.06 CON16.35@4202.76,3851.92
  Bottom Layer w4: v1(4202.45,3906.37) 4202.45,3985.38 4182.53,4005.29 4182.53,4182.98 4757.22,4757.66 4773.72,4757.66 4791.98,4775.92 4791.98,4792.42 5359.4,5359.84 6126.78,5359.84 6287.85,5520.92 6346.15,5520.92 6371.03,5496.04 R538.1@6371.03,5403.53 6378.18,5396.37 U37.1@6378.18,5374.57
SDIO_A_SEL: R305.1 U35.16 | length 2137.6
  Top Layer w4: R305.1@6017.19,4624.15 6017.19,4605.85 v1(6017.59,4605.45)
  L6 w4: v1(5502.98,2920.85) 5521.31,2902.52 5776.78,2902.52 5891.76,3017.49 5891.76,4454.11 6017.59,4579.94 v1(6017.59,4605.45)
  Bottom Layer w4: v1(5502.98,2920.85) 5504.55,2922.42 U35.16@5504.55,2954.86
SDIO_A_WP: CON16.33 R429.1 | length 85.8
  Top Layer w4: v1(4183.05,3917.98) 4183.05,3852.6 4183.4,3852.25 CON16.33@4183.07,3851.92
  Bottom Layer w4: v1(4183.05,3917.98) 4184.13,3919.06 R429.1@4184.13,3936.97
SDIO_B_CD#: CON16.27 R430.1 | length 86.4
  Top Layer w4: v1(4123.67,3907.32) 4124.02,3906.98 CON16.27@4124.02,3851.92
  Bottom Layer w4: R430.1@4120.8,3936.97 4120.8,3910.19 v1(4123.67,3907.32)
SDIO_B_CLK: CON16.21 TP31.1 U49.M6 | length 1531.6
  Top Layer w6.5: CON16.21@4064.96,3851.92 4064.96,3927.84 4158.91,4021.79 4158.91,4084.94 4158.91,4088.19 cw(c4164.46,4088.19) 4164.46,4093.74 4171.86,4093.74 ccw(c4171.86,4099.29) 4177.41,4099.29 4177.41,4168.43 ccw(c4171.86,4168.43) 4171.86,4173.98 4164.46,4173.98 ccw(c4164.46,4168.43) 4158.91,4168.43 4158.91,4117.79 cw(c4153.36,4117.79) 4153.36,4112.24 4145.96,4112.24 cw(c4145.96,4117.79) 4140.41,4117.79 4140.41,4200.43 cw(c4145.96,4200.43) 4145.96,4205.98 4153.36,4205.98 ccw(c4153.36,4211.53) 4158.91,4211.53 4158.91,4214.78 4158.91,4286.28 v1(4161.56,4288.94) ; v1(4368.31,5038.35) 4375.78,5030.88 U49.M6@4385.88,5030.88
  Bottom Layer w6: v1(4161.56,4288.94) 4161.56,4447.14 4298.34,4583.91 4298.34,5003.27 4333.42,5038.35 v1(4368.31,5038.35)
SDIO_B_CMD: CON16.25 R398.2 TP30.1 U49.M5 | length 1531.6
  Top Layer w6.5: CON16.25@4104.33,3851.92 4104.33,3913.91 4199.73,4009.31 4199.73,4176.6 4199.73,4179.85 ccw(c4194.18,4179.85) 4194.18,4185.4 4186.78,4185.4 cw(c4186.78,4190.95) 4181.23,4190.95 4181.23,4275.67 cw(c4186.78,4275.67) 4186.78,4281.22 4194.18,4281.22 cw(c4194.18,4275.67) 4199.73,4275.67 4199.73,4209.45 ccw(c4205.28,4209.45) 4205.28,4203.9 4212.68,4203.9 ccw(c4212.68,4209.45) 4218.23,4209.45 4218.23,4295.58 ccw(c4212.68,4295.58) 4212.68,4301.13 4205.28,4301.13 cw(c4205.28,4306.68) 4199.73,4306.68 4199.73,4309.93 v1(4199.73,4331.87) ; v1(4367.28,5010.34) 4368.14,5011.2 U49.M5@4385.88,5011.2
  Bottom Layer w6: v1(4199.73,4331.87) 4199.73,4417.01 4356.91,4574.2 4356.91,4955.03 TP30.1@4348.31,4963.64 4348.31,5001.3 4357.35,5010.34 v1(4367.28,5010.34) 4367.67,5009.95 R398.2@4389.89,5009.95
SDIO_B_D0: CON16.5 R397.2 TP29.1 U49.A3 | length 1531.6
  Top Layer w3: 4152.57,4971.83 U49.A3@4169.35,4971.83
  Top Layer w6: CON16.5@3907.48,3851.92 3907.48,3916.24 3886.4,3937.33 3886.4,4028.54 3940.21,4082.35 3940.21,4742.06 v1(3942.2,4744.05) ; v1(4124.21,4954.34) 4135.08,4954.34 4152.57,4971.83
  Bottom Layer w6: v1(3942.2,4744.05) 3988.16,4744.05 4007.19,4763.07 4007.19,4773.18 4007.19,4776.18 ccw(c4001.79,4776.18) 4001.79,4781.58 3994.59,4781.58 cw(c3994.59,4786.98) 3989.19,4786.98 3989.19,4866.17 cw(c3994.59,4866.17) 3994.59,4871.57 4001.79,4871.57 cw(c4001.79,4866.17) 4007.19,4866.17 4007.19,4804.98 ccw(c4012.59,4804.98) 4012.59,4799.58 4019.79,4799.58 ccw(c4019.79,4804.98) 4025.19,4804.98 4025.19,4887.35 ccw(c4019.79,4887.35) 4019.79,4892.75 4012.59,4892.75 cw(c4012.59,4898.15) 4007.19,4898.15 4007.19,4901.15 4007.19,4914.43 4047.09,4954.34 v1(4124.21,4954.34)
SDIO_B_D1: CON16.3 U49.A4 | length 1531.4
  Top Layer w6: CON16.3@3887.8,3851.92 v1(3887.81,3906.63) ; v1(4043.79,4135.88) 4039.84,4139.83 4039.84,4953.28 4077.85,4991.28 U49.A4@4169.13,4991.28
  Bottom Layer w6: v1(3887.81,3906.63) 3887.81,3954.96 3887.81,3957.96 ccw(c3881.81,3957.96) 3881.81,3963.96 3840.47,3963.96 cw(c3840.47,3968.46) 3835.97,3968.46 3835.97,3977.46 cw(c3840.47,3977.46) 3840.47,3981.96 3890.84,3981.96 ccw(c3890.84,3986.46) 3895.34,3986.46 3895.34,3995.46 ccw(c3890.84,3995.46) 3890.84,3999.96 3859.89,3999.96 cw(c3859.89,4004.46) 3855.39,4004.46 3855.39,4013.46 cw(c3859.89,4013.46) 3859.89,4017.96 3881.81,4017.96 ccw(c3881.81,4023.96) 3887.81,4023.96 3887.81,4042.69 3887.81,4068.48 3955.21,4135.88 v1(4043.79,4135.88)
SDIO_B_D2: CON16.7 U49.A5 | length 1650.3
  Top Layer w3: 4142.53,5022.56 4153.88,5011.2 U49.A5@4169.35,5011.2
  Top Layer w6: CON16.7@3927.17,3851.92 3927.17,3933.76 3927.17,3936.76 ccw(c3921.77,3936.76) 3921.77,3942.16 3914.57,3942.16 cw(c3914.57,3947.56) 3909.17,3947.56 3909.17,4026.81 cw(c3914.57,4026.81) 3910.73,4030.62 3949.1,4068.99 cw(c3952.92,4065.17) 3956.74,4068.99 3961.83,4063.9 cw(c3958.01,4060.08) 3961.83,4056.26 3928.73,4023.16 ccw(c3932.57,4019.36) 3927.17,4019.36 3927.17,3966.41 ccw(c3932.57,3966.41) 3932.57,3961.01 3939.77,3961.01 ccw(c3939.77,3966.41) 3945.17,3966.41 3945.17,4011.9 cw(c3950.57,4011.9) 3946.73,4015.71 3987.3,4056.27 ccw(c3983.47,4060.08) 3987.29,4063.9 3982.19,4068.99 cw(c3986.02,4072.81) 3982.2,4076.62 3984.32,4078.75 4001.08,4095.51 4001.08,4131.05 4001.08,4134.05 ccw(c3995.08,4134.05) 3995.08,4140.05 3985.47,4140.05 cw(c3985.47,4144.55) 3980.97,4144.55 3980.97,4153.55 cw(c3985.47,4153.55) 3985.47,4158.05 3995.08,4158.05 ccw(c3995.08,4164.05) 4001.08,4164.05 4001.08,4379.42 4001.08,4957.86 4065.77,5022.56 4142.53,5022.56
SDIO_B_D3: CON16.9 U49.B2 | length 1532.6
  Top Layer w3: 4179.09,4915.87 4179.09,4942.2 U49.B2@4189.03,4952.14
  Top Layer w6: CON16.9@3946.85,3851.92 3947.87,3851.92 v1(3947.87,3906.28) ; v1(4128.97,4075.79) 4119.09,4085.68 4119.09,4855.87 4179.09,4915.87
  Bottom Layer w6: v1(3947.87,3906.28) 3935.25,3918.9 3935.25,3980.98 3938.33,3984.06 3940.45,3986.18 4014.92,4060.65 ccw(c4011.1,4064.47) 4014.92,4068.29 4009.82,4073.38 ccw(c4006.01,4069.56) 4002.19,4073.38 3946.4,4017.6 cw(c3942.59,4021.42) 3938.77,4017.6 3933.68,4022.69 cw(c3937.5,4026.51) 3933.68,4030.33 4002.2,4098.85 cw(c4006.01,4095.02) 4009.81,4098.85 4027.63,4081.03 ccw(c4031.46,4084.83) 4035.28,4081.02 4037.4,4083.14 4051.08,4096.82 4107.95,4096.82 v1(4128.97,4075.79)
SDIO_B_D4: CON16.11 U49.B3 | length 1531.5
  Top Layer w3: 4157.86,4961.96 4179.16,4961.96 U49.B3@4189.03,4971.83
  Top Layer w6: CON16.11@3966.54,3851.92 3966.54,3930.99 v1(3968.62,3933.07) ; v1(4096.21,4055.04) 4094.51,4056.74 4094.51,4860.23 4122.16,4887.88 4122.16,4926.27 4157.86,4961.96
  Bottom Layer w6: v1(3968.62,3933.07) 3974.24,3933.07 3979.68,3938.52 3983.12,3941.95 3983.35,3943.79 ccw(c3977.99,3944.46) 3981.8,3948.27 3964,3966.08 cw(c3967.8,3969.91) 3963.97,3973.72 4055.37,4065.11 cw(c4059.19,4061.29) 4063,4065.11 4068.1,4060.02 cw(c4064.28,4056.2) 4068.1,4052.38 3989.44,3973.73 ccw(c3993.26,3969.91) 3989.44,3966.09 3994.53,3961 ccw(c3998.35,3964.82) 4002.17,3961 4084.64,4043.48 4086.76,4045.6 v1(4096.21,4055.04)
SDIO_B_D5: CON16.13 U49.B4 | length 1531.6
  Top Layer w3: 4138.38,4974.81 4145.25,4981.68 4179.21,4981.68 U49.B4@4189.03,4991.51
  Top Layer w6: CON16.13@3986.22,3851.92 3986.22,3905.98 v1(3986.45,3906.21) ; v1(4126.96,4034.4) 4113.06,4020.5 4075.63,4020.5 4063.46,4032.67 4063.46,4954.3 4083.98,4974.81 4138.38,4974.81
  Bottom Layer w6: v1(3986.45,3906.21) 3997.98,3906.21 4034.03,3942.26 4034.03,3960.47 4043.43,3969.88 4045.55,3972 cw(c4049.37,3968.18) 4053.19,3972 4071,3954.19 ccw(c4074.83,3958) 4078.63,3954.16 4111.29,3986.82 ccw(c4107.47,3990.64) 4111.29,3994.46 4106.2,3999.55 ccw(c4102.38,3995.73) 4098.56,3999.55 4078.64,3979.63 cw(c4074.83,3983.45) 4071.01,3979.63 4065.92,3984.73 cw(c4069.73,3988.54) 4065.92,3992.36 4102.08,4028.52 4104.2,4030.65 4107.95,4034.4 v1(4126.96,4034.4)
SDIO_B_D6: CON16.15 U49.B5 | length 1650
  Top Layer w3: 4147.71,5001.33 4179.16,5001.33 U49.B5@4189.03,5011.2
  Top Layer w6: CON16.15@4005.91,3851.92 4005.91,3913.7 4024.15,3931.94 4024.15,3949.02 4024.15,3952.02 ccw(c4018.75,3952.02) 4018.75,3957.42 3975.55,3957.42 cw(c3975.55,3962.82) 3970.15,3962.82 3970.15,4012.92 cw(c3975.55,4012.92) 3975.55,4018.32 3982.75,4018.32 cw(c3982.75,4012.92) 3988.15,4012.92 3988.15,3980.82 ccw(c3993.55,3980.82) 3993.55,3975.42 4000.75,3975.42 ccw(c4000.75,3980.82) 4006.15,3980.82 4006.15,4041.23 cw(c4011.55,4041.23) 4011.55,4046.63 4018.75,4046.63 cw(c4018.75,4041.23) 4024.15,4041.23 4024.15,3980.82 ccw(c4029.55,3980.82) 4029.55,3975.42 4036.75,3975.42 ccw(c4036.75,3980.82) 4042.15,3980.82 4042.15,4059.23 ccw(c4036.75,4059.23) 4036.75,4064.63 4029.55,4064.63 cw(c4029.55,4070.03) 4024.15,4070.03 4024.15,4073.03 4024.15,4956.26 4076.54,5008.65 4140.38,5008.65 4147.71,5001.33
SDIO_B_D7: CON16.17 U49.B6 | length 1531.8
  Top Layer w3: 4139.88,5038.63 4157.65,5020.87 4179.02,5020.87 U49.B6@4189.03,5030.88
  Top Layer w6: v1(3962.34,4091.03) 3964.82,4093.51 3964.82,4947.5 4055.96,5038.63 4139.88,5038.63 ; v1(4025.49,3908.73) 4025.59,3908.63 CON16.17@4025.59,3851.92 CON16.17@4026.15,3852.48
  Bottom Layer w6: v1(3962.34,4091.03) 3913.78,4042.46 3913.78,3900.18 3934.27,3879.69 3996.45,3879.69 v1(4025.49,3908.73)
SDIO_B_IOPWR: C310.2 C357.1 C358.1 C359.1 CON16.1 R397.1 R398.1 U49.C6 U49.M4 U49.N4 U49.P3 U49.P5 | length 2044.1
  Top Layer w6.5: v1(4366.43,4989.86) 4368.08,4991.51 U49.M4@4385.88,4991.51 U49.N4@4405.57,4991.51
  Top Layer w8: 3862.14,3907.85 3868.11,3901.88 CON16.1@3868.11,3851.92
  Top Layer w10: U49.C6@4208.72,5030.88 4217.96,5030.88 v1(4228.47,5041.39) ; U49.P3@4425.25,4971.83 4443.08,4971.83 v1(4443.52,4971.39) ; U49.P5@4425.25,5011.2 4425.91,5011.85 v1(4442.8,5011.85)
  Top Layer w20: 3862.14,3907.85 3847.88,3922.11 3847.88,4031.15 3911.09,4094.36 3911.09,4766.33 v1(3919.39,4774.63)
  L3 w20: v1(3919.39,4774.63) 3919.39,4861.21 3972.61,4914.43 v1(4086.57,4914.43) 4135.58,4914.43 4188.51,4967.36 ; v1(4228.47,5041.39) 4188.51,5001.42 4188.51,4967.36 ; v1@4368.72,4987.58 4384.91,4971.39 ; v1@4443.52,5010.13 v1(4443.52,4971.39) 4384.91,4971.39 ; 4188.51,4967.36 4219.87,4935.99 4349.51,4935.99 4384.91,4971.39
  Bottom Layer w6.5: v1(4366.43,4989.86) 4366.84,4990.26 R398.1@4389.89,4990.26
  Bottom Layer w8: v1(4086.57,4914.43) 4086.57,4924.19 R397.1@4095.39,4933.01
  Bottom Layer w10: C310.2@4201.84,5020.93 4204.31,5023.39 C357.1@4204.31,5050.56 4219.29,5050.56 v1(4228.47,5041.39) ; v1(4442.8,5011.85) 4444.01,5013.06 C359.1@4464.24,5013.06 ; v1@4443.53,4971.39 C358.1@4465.72,4971.39
SDIO_B_PWR_EN: CON16.120 R432.1 | length 1234.4
  Top Layer w4: CON16.120@5029.52,3666.87 5029.52,3644.94 5053.48,3644.94 v1(5054.67,3646.12)
  Bottom Layer w4: v1(5054.67,3646.12) 5078.38,3646.12 5156.51,3567.99 5156.51,3150.27 5283.7,3023.08 5283.7,2622.91 R432.1@5322.47,2584.14
SDIO_B_WP: CON16.29 R433.1 | length 86
  Top Layer w4: CON16.29@4143.7,3851.92 4145.2,3853.42 v1(4145.2,3918.09)
  Bottom Layer w4: v1(4145.2,3918.09) 4146.05,3918.94 R433.1@4146.05,3936.97
SLEEVE: CON4.1 D21.1 U20.8 U20.10 | length 1477.5
  Top Layer w8: CON4.1@4938.89,114.17 4946.74,122.02 4946.74,544.94 5070.76,668.96 5210,668.96 5217.48,661.48 U20.8@5217.48,650.24 ; 5124.32,591.18 U20.10@5178.11,591.18
  Top Layer w15: D21.1@4871.84,115.51 4937.55,115.51 CON4.1@4938.89,114.17
  Top Layer w30: CON4.1@4938.89,114.17 4947.06,114.17 4994.07,161.18 4994.07,507.28 5078.2,591.42 5124.09,591.42
SPI_A_/HOLD_(IO3): CON17.15 J44.5 | length 1468.8
  Top Layer w6: J44.5@2893.38,1301.44 2938.91,1301.44 v1(2972.57,1335.1) ; v1@3316.93,2490.05 CON17.15@3316.93,2565.4
  L3 w5: v1(2972.57,1335.1) 2977.26,1335.1 2999.4,1357.24 2999.4,2097.66 3316.92,2415.18 v1(3316.92,2490.03)
SPI_A_/WP_(IO2): CON17.11 J44.2 | length 1464.1
  Top Layer w6: v1(3099.67,1463.92) 3117.79,1482.04 J44.2@3117.79,1501.44 ; v1(3355.44,2487.49) 3356.3,2488.35 CON17.11@3356.3,2565.4
  L3 w5: v1(3099.67,1463.92) 3089.27,1474.33 3089.27,1495.2 3089.27,1517.7 cw(c3094.27,1517.7) 3094.27,1522.7 3102.45,1522.7 ccw(c3102.45,1527.7) 3107.45,1527.7 3107.45,1537.7 ccw(c3102.45,1537.7) 3102.45,1542.7 3084.45,1542.7 cw(c3084.45,1547.7) 3079.45,1547.7 3079.45,1557.7 cw(c3084.45,1557.7) 3084.45,1562.7 3102.45,1562.7 ccw(c3102.45,1567.7) 3107.45,1567.7 3107.45,1577.7 ccw(c3102.45,1577.7) 3102.45,1582.7 3084.45,1582.7 cw(c3084.45,1587.7) 3079.45,1587.7 3079.45,1597.7 cw(c3084.45,1597.7) 3084.45,1602.7 3102.45,1602.7 ccw(c3102.45,1607.7) 3107.45,1607.7 3107.45,1617.7 ccw(c3102.45,1617.7) 3102.45,1622.7 3084.45,1622.7 cw(c3084.45,1627.7) 3079.45,1627.7 3079.45,1637.7 cw(c3084.45,1637.7) 3084.45,1642.7 3102.45,1642.7 ccw(c3102.45,1647.7) 3107.45,1647.7 3107.45,1657.7 ccw(c3102.45,1657.7) 3102.45,1662.7 3084.45,1662.7 cw(c3084.45,1667.7) 3079.45,1667.7 3079.45,1677.7 cw(c3084.45,1677.7) 3084.45,1682.7 3095.09,1682.7 ccw(c3095.09,1687.7) 3100.09,1687.7 3100.09,1697.7 ccw(c3095.09,1697.7) 3095.09,1702.7 3094.27,1702.7 cw(c3094.27,1707.7) 3089.27,1707.7 3089.27,1755.62 3089.27,2121.27 3355.44,2387.44 v1(3355.44,2487.49)
SPI_A_CS0#: CON17.9 J44.6 | length 1372.7
  Top Layer w5: v1(3375.8,2505.3) 3375.99,2505.49 CON17.9@3375.99,2565.4
  Top Layer w6: v1(3115.68,1338.34) 3115.68,1303.56 J44.6@3117.79,1301.44
  L3 w5: v1(3115.68,1338.34) 3133.37,1356.03 3133.37,1583.52 3133.37,1744.6 3133.37,2131.4 3375.8,2373.83 v1(3375.8,2505.3)
"SPI_A_CS1# / GPIO_A_6": CON17.7 J27.1 | length 1346.2
  Top Layer w5: v1(3258.34,1700.57) 3248.92,1700.57 3221.03,1672.68 3221.03,1397.81 J27.1@3283.55,1335.29
  Top Layer w6: CON17.7@3395.67,2565.4 3395.67,2474.74 v1(3396.24,2474.18)
  L3 w5: v1@3258.19,1700.71 3258.19,2193.35 3410.69,2345.85 3410.69,2459.72 v1(3396.24,2474.18)
SPI_A_SCK: CON17.21 J44.3 | length 1465
  Top Layer w6: J44.3@2893.38,1401.44 2909.19,1417.25 v1(2909.19,1436.03) ; CON17.21@3257.88,2565.4 3257.88,2509.5 v1(3258.36,2509.02)
  L3 w5: v1(2909.19,1436.03) 2906.61,1438.61 2906.61,1479.15 2906.61,1481.65 ccw(c2901.61,1481.65) 2901.61,1486.65 2883.08,1486.65 cw(c2883.08,1491.65) 2878.08,1491.65 2878.08,1501.65 cw(c2883.08,1501.65) 2883.08,1506.65 2905.8,1506.65 ccw(c2905.8,1511.65) 2910.8,1511.65 2910.8,1521.65 ccw(c2905.8,1521.65) 2905.8,1526.65 2883.08,1526.65 cw(c2883.08,1531.65) 2878.08,1531.65 2878.08,1541.65 cw(c2883.08,1541.65) 2883.08,1546.65 2905.8,1546.65 ccw(c2905.8,1551.65) 2910.8,1551.65 2910.8,1561.65 ccw(c2905.8,1561.65) 2905.8,1566.65 2890.41,1566.65 cw(c2890.41,1571.65) 2885.41,1571.65 2885.41,1581.65 cw(c2890.41,1581.65) 2890.41,1586.65 2901.61,1586.65 ccw(c2901.61,1591.65) 2906.61,1591.65 2906.61,1612.13 2906.61,2078.91 3258.36,2430.66 v1(3258.36,2509.02)
SPI_A_SDI_(IO1): CON17.13 J44.4 | length 1465.3
  Top Layer w6: v1(3036.75,1398.21) 3114.56,1398.21 J44.4@3117.79,1401.44 ; CON17.13@3336.62,2565.4 3336.62,2508 v1(3337.11,2507.51)
  L3 w5: v1(3036.75,1398.21) 3057.71,1419.16 3057.71,1448.28 3057.71,1450.78 ccw(c3052.71,1450.78) 3052.71,1455.78 3036.71,1455.78 cw(c3036.71,1460.78) 3031.71,1460.78 3031.71,1470.78 cw(c3036.71,1470.78) 3036.71,1475.78 3055.36,1475.78 ccw(c3055.36,1480.78) 3060.36,1480.78 3060.36,1490.78 ccw(c3055.36,1490.78) 3055.36,1495.78 3037.24,1495.78 cw(c3037.24,1500.78) 3032.24,1500.78 3032.24,1510.78 cw(c3037.24,1510.78) 3037.24,1515.78 3052.71,1515.78 ccw(c3052.71,1520.78) 3057.71,1520.78 3057.71,1545.18 3057.71,2122.77 3337.11,2402.17 v1(3337.11,2507.51)
SPI_A_SDO_(IO0): CON17.17 J44.1 | length 1470.3
  Top Layer w6: J44.1@2893.38,1501.44 2927.46,1501.44 2944.02,1518.01 v1(2944.02,1537.4) ; v1(3297.07,2509.55) 3297.25,2509.73 CON17.17@3297.25,2565.4
  L3 w5: v1(2944.02,1537.4) 2943.95,1537.47 2943.95,1552.9 2943.95,1575.41 cw(c2948.95,1575.41) 2948.95,1580.41 2966.42,1580.41 ccw(c2966.42,1585.41) 2971.42,1585.41 2971.42,1595.41 ccw(c2966.42,1595.41) 2966.42,1600.41 2942.06,1600.41 cw(c2942.06,1605.41) 2937.06,1605.41 2937.06,1615.41 cw(c2942.06,1615.41) 2942.06,1620.41 2966.42,1620.41 ccw(c2966.42,1625.41) 2971.42,1625.41 2971.42,1635.41 ccw(c2966.42,1635.41) 2966.42,1640.41 2942.06,1640.41 cw(c2942.06,1645.41) 2937.06,1645.41 2937.06,1655.41 cw(c2942.06,1655.41) 2942.06,1660.41 2966.42,1660.41 ccw(c2966.42,1665.41) 2971.42,1665.41 2971.42,1675.41 ccw(c2966.42,1675.41) 2966.42,1680.41 2942.06,1680.41 cw(c2942.06,1685.41) 2937.06,1685.41 2937.06,1695.41 cw(c2942.06,1695.41) 2942.06,1700.41 2962.58,1700.41 ccw(c2962.58,1705.41) 2967.58,1705.41 2967.58,1715.41 ccw(c2962.58,1715.41) 2962.58,1720.41 2948.95,1720.41 cw(c2948.95,1725.41) 2943.95,1725.41 2943.95,1749.17 2943.95,2078.08 3297.07,2431.19 v1(3297.07,2509.55)
SPI_B_MCU_CS0#: CON18.74 J19.1 | length 1602.6
  Top Layer w4: J19.1@4070.39,1512.78 4139.5,1512.78 4146.7,1519.97 4146.7,1758.08 4224.91,1836.3 v1(4238.12,1836.3)
  Top Layer w6: CON18.74@4320.87,2750.44 v1@4320.87,2827.49
  L3 w5: v1(4238.12,1836.3) 4238.12,2186.84 4168.52,2256.45 4168.52,2562.35 4321.73,2715.56 v1(4321.73,2828.35)
"SPI_B_MCU_CS1# / GPIO_A_7": C73.1 CON18.76 J19.3 R536.1 | length 7679.3
  Top Layer w4: J19.3@4070.39,1412.78 4139.05,1412.78 4158.42,1432.15 4158.42,1745.95 v1(4229.2,1816.73)
  Top Layer w6: CON18.76@4301.18,2750.44 v1@4301.18,2810.35
  L3 w5: v1(4229.2,1816.73) 4221.71,1824.22 4221.71,2186.1 4155.54,2252.27 4155.54,2565.53 4301.37,2711.36 v1(4301.37,2810.54)
  L6 w5: v1(1939.54,5022.22) 1965.18,5022.22 2328.58,4658.82 4255.38,4658.82 4301.37,4612.83 4301.37,4302.83 4340.31,4263.89 4340.31,4094.86 4283.28,4037.83 4283.28,3905.3 4314.83,3873.75 4314.83,2850.83 4301.37,2837.37 v1(4301.37,2810.54)
  Bottom Layer w5: R536.1@792.3,6125.18 836.58,6125.18 1001.19,5960.57 1001.19,5911.86 1066.74,5846.31 1115.45,5846.31 v1(1939.54,5022.22)
SPI_B_MCU_SCK: CON18.66 J19.5 | length 1911.4
  Top Layer w6: J19.5@4070.39,1312.78 4026.18,1312.78 3992.38,1346.57 3992.38,1700.49 3996.71,1704.82 4015.8,1723.91 cw(c4024.29,1715.43) 4032.77,1723.91 4055.39,1701.3 ccw(c4063.87,1709.78) 4072.36,1701.3 ccw(c4063.87,1709.78) 4072.36,1718.27 4049.74,1740.88 cw(c4058.23,1749.37) 4049.74,1757.85 4080.32,1788.43 4159.47,1867.58 v1(4159.47,2163.51) ; CON18.66@4399.61,2750.44 v1@4399.61,2827.49
  Bottom Layer w6: v1(4159.47,2163.51) 4159.47,2193.77 4159.24,2193.99 4159.24,2551.15 4400.47,2792.37 v1(4400.47,2828.35)
SPI_B_MCU_SDI: CON18.70 J19.7 | length 1911.8
  Top Layer w6: J19.7@4070.39,1212.78 4033.9,1212.78 3976.93,1269.74 3976.93,1712.53 4142.43,1878.03 v1(4142.43,2183.91) ; CON18.70@4360.24,2750.44 v1@4360.24,2827.49
  Bottom Layer w6: v1(4142.43,2183.91) 4145.38,2186.85 4145.38,2555.8 4361.1,2771.52 v1(4361.1,2828.35)
SPI_B_MCU_SDO: CON18.72 J19.9 | length 1984.8
  Top Layer w6: J19.9@4070.39,1112.78 4028.7,1112.78 3978.26,1163.21 3978.26,1246.95 3960.82,1264.39 3960.82,1728.38 4124.5,1892.07 v1(4124.5,2162.57) ; CON18.72@4340.55,2750.44 v1@4340.55,2810.35
  Bottom Layer w6: v1(4124.5,2162.57) 4124.5,2191.72 4132.72,2199.93 4132.72,2566.35 4340.74,2774.37 v1(4340.74,2810.54)
SPI_C_CS0#: CON18.58 J19.10 | length 2072.2
  Top Layer w4: J19.10@4294.8,1112.78 4225.44,1112.78 4185.36,1152.86 4185.36,1540.31 4229.29,1584.24 v1(4301.81,1584.24)
  Top Layer w6: CON18.58@4478.35,2750.44 v1@4478.35,2827.49
  Bottom Layer w4: v1(4301.81,1584.24) 4301.81,1596.66 4266.35,1632.12 4266.35,2418.82 4340.68,2493.16 4340.68,2666.81 4478.85,2804.98 4478.85,2827.99 v1(4479.21,2828.35)
SPI_C_SCK: CON18.54 J19.6 | length 1893.5
  Top Layer w6: J19.6@4294.8,1312.78 4223.28,1312.78 4199.68,1336.37 4199.68,1537.15 4228.2,1565.66 v1(4321.66,1565.66) ; CON18.54@4517.72,2750.44 v1@4517.72,2827.49
  Bottom Layer w6: v1(4321.66,1565.66) 4321.66,1599.47 4282.18,1638.95 4282.18,2419.41 4342.25,2479.48 4353.63,2490.87 4353.63,2656.65 4518.58,2821.6 v1(4518.58,2828.35)
SPI_C_SDI: CON18.50 J19.4 | length 1836.9
  Top Layer w6: J19.4@4294.8,1412.78 4224.94,1412.78 4212.82,1424.9 4212.82,1529.04 4232.66,1548.88 v1(4354.47,1548.88) ; CON18.50@4557.09,2750.44 v1@4557.09,2827.49
  Bottom Layer w6: v1(4354.47,1548.88) 4354.47,1592.77 4299.82,1647.42 4299.82,2418.34 4368.35,2486.86 4368.35,2647.35 4531.28,2810.28 4547.93,2810.28 4557.95,2820.3 v1(4557.95,2828.35)
SPI_C_SDO: CON18.48 J19.2 | length 1836.3
  Top Layer w6: J19.2@4294.8,1512.78 4366.17,1512.78 v1(4376.29,1522.9) ; CON18.48@4576.77,2750.44 v1@4576.77,2810.35
  Bottom Layer w6: v1(4376.29,1522.9) 4376.29,1596.65 4318.05,1654.89 4317.02,1655.92 4317.02,1678.89 cw(c4327.52,1678.89) 4327.52,1689.39 4355.41,1689.39 ccw(c4355.41,1699.89) 4355.41,1710.39 4320.32,1710.39 cw(c4320.32,1720.89) 4320.32,1731.39 4355.41,1731.39 ccw(c4355.41,1741.89) 4355.41,1752.39 4320.32,1752.39 cw(c4320.32,1762.89) 4320.32,1773.39 4350.89,1773.39 ccw(c4350.89,1783.89) 4350.89,1794.39 4327.52,1794.39 cw(c4327.52,1804.89) 4317.02,1804.89 4317.02,1828.14 4317.02,2416.62 4382.65,2482.24 4382.65,2636.52 4535.06,2788.94 4555.36,2788.94 v1(4576.96,2810.54)
SPK_N: R50.2 R208.1 U19.22 | length 213.9
  Top Layer w12: 5178.53,937.46 U19.22@5178.53,956.94
  Top Layer w15: 5178.53,937.46 5178.53,932.26 5267.16,843.64 5324.18,843.64 R208.1@5329.03,848.5
SPK_P: R207.1 R274.2 U19.21 | length 277.4
  Top Layer w12: 5158.85,925.63 U19.21@5158.85,956.94
  Top Layer w15: 5158.85,925.63 5158.85,919.38 5165.46,912.77 5165.46,877.3 5236.14,806.62 5324.1,806.62 R207.1@5329.1,801.62
SPKOUT_N: C213.2 C214.1 J6.1 R208.2 | length 209.8
  Top Layer w15: R208.2@5359.12,847.44 5360.98,849.3 C214.1@5390.2,849.3 5415.15,849.3 C213.2@5424.25,840.19 5446.48,840.19 5513.18,906.9 J6.1@5536.71,906.9
SPKOUT_P: C211.1 C213.1 J6.2 R207.2 | length 184.3
  Top Layer w15: R207.2@5359.41,803.14 5362.19,800.36 C211.1@5390.18,800.36 5413.94,800.36 C213.1@5424.25,810.67 5532.95,810.67 J6.2@5536.71,806.9
SW4: C66.2 L7.1 U4.32
TEST_GENERIC/TEST_BOUNDARY_SCAN: CON15.64 R235.1 R608.1 | length 181.6
  Top Layer w5: v1(2895.19,3525.82) 2903.55,3534.18 CON15.64@2903.55,3666.88
  Bottom Layer w5: R608.1@2894.83,3544.74 2894.83,3526.18 v1(2895.19,3525.82) 2895.68,3525.33 R235.1@2895.68,3507.99
TIP: C201.1 CON4.2 D20.1 FB5.2 U20.14 | length 1162.9
  Top Layer w8: U20.14@5237.16,512.44 5237.16,464.51 v1(5245.24,456.43)
  Top Layer w15: CON4.2@5269.69,311.11 D20.1@5385.65,311.11
  Top Layer w17: CON4.2@5269.6,311.02 5269.69,311.11 5319.6,361.02 5381.73,361.02 5476.39,455.69 5476.39,655.56 5398.62,733.33 v1(5313.55,733.33)
  Bottom Layer w17: FB5.2@5144.76,736.93 5178.75,736.93 C201.1@5178.91,737.09 5182.71,733.3 v1@5313.52,733.3
  Bottom Layer w20: v1(5245.24,456.43) 5263.82,437.85 5263.82,316.8 CON4.2@5269.6,311.02
TS: J3.2 R69.1 R71.2 TP5.1 U9.16 | length 355.7
  Top Layer w8: J3.2@1736.35,126.7 1736.35,168.99 1790.98,223.63 1790.98,281.46 1790.98,284.6 v1(1792.86,286.48) ; U9.16@1770.69,413.72 1770.69,388.63 1793.18,366.14 R71.2@1793.18,340.94 ; TP5.1@1790.11,281.46 TP5.1@1790.11,286.48 ; TP5.1@1793.18,286.8 1793.18,300.9 R71.2@1793.18,340.94 ; R69.1@1823.14,343.92 1820.16,340.94 R71.2@1793.18,340.94
TUSB_A_ID: R560.1 U5.2 U51.9 | length 186.1
  Bottom Layer w5: U51.9@3784.16,228.43 3784.16,212.9 3795.93,201.13 R560.1@3795.93,191.07 3785.48,180.62 3785.48,95.92 3792.88,88.52 3803.52,88.52 3810.06,81.97 U5.2@3810.06,67.94
TUSB_C_ID: R151.1 U6.2 U13.9 | length 134.9
  Bottom Layer w5: U6.2@2563.75,6199.45 R151.1@2563.75,6118.73 2563.75,6098.73 2585.33,6077.15 U13.9@2585.33,6073.52
TUSB_D_ID: R166.1 U16.9 U62.2 | length 147.5
  Bottom Layer w6: U62.2@4005.51,6202.11 4005.49,6186.92 3991.67,6173.09 R166.1@3991.67,6117.74 3991.67,6088.77 4010.05,6070.38 U16.9@4010.05,6067.99
U28_SW1: C96.2 L8.1 U9.28 | length 30.6
  Bottom Layer w10: C96.2@1640.77,513.13 1645.97,518.34 v2(1669.18,518.34)
  other v2: 1668.51,496.84 1690.13,496.84 1690.8,518.34
  other v4: 1642.54,681.02 1642.54,711.28 1642.54,739.9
